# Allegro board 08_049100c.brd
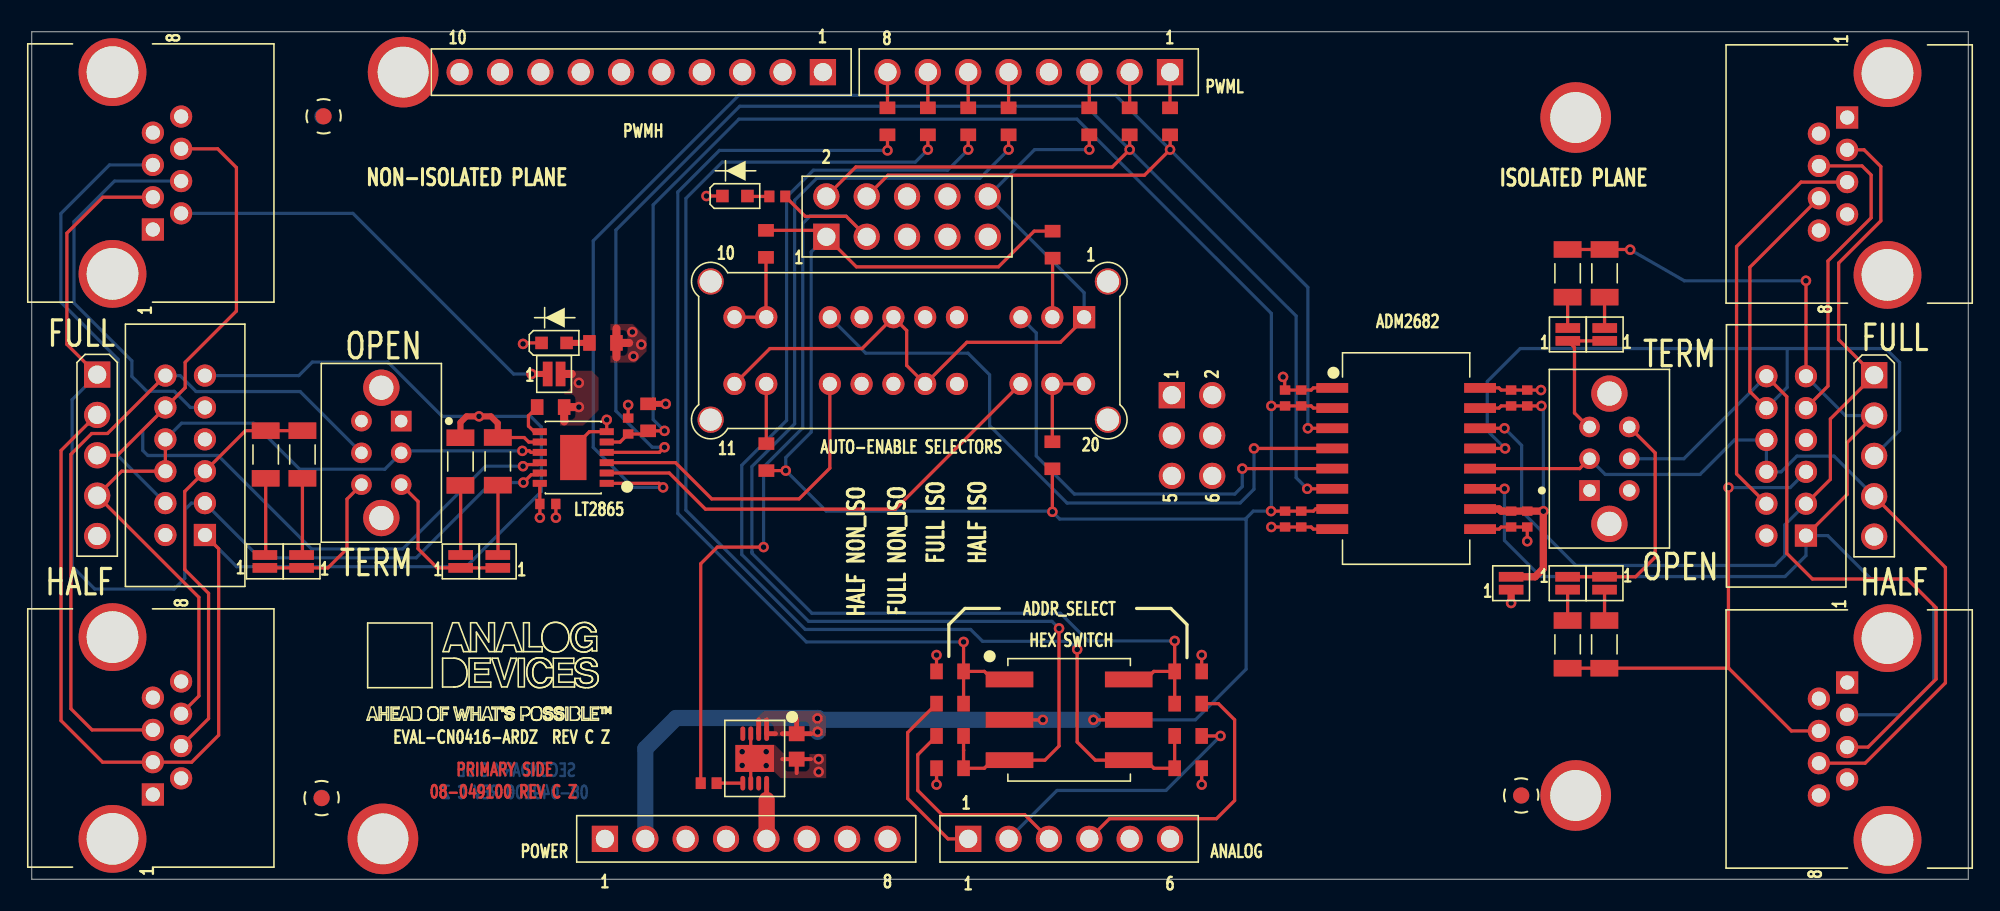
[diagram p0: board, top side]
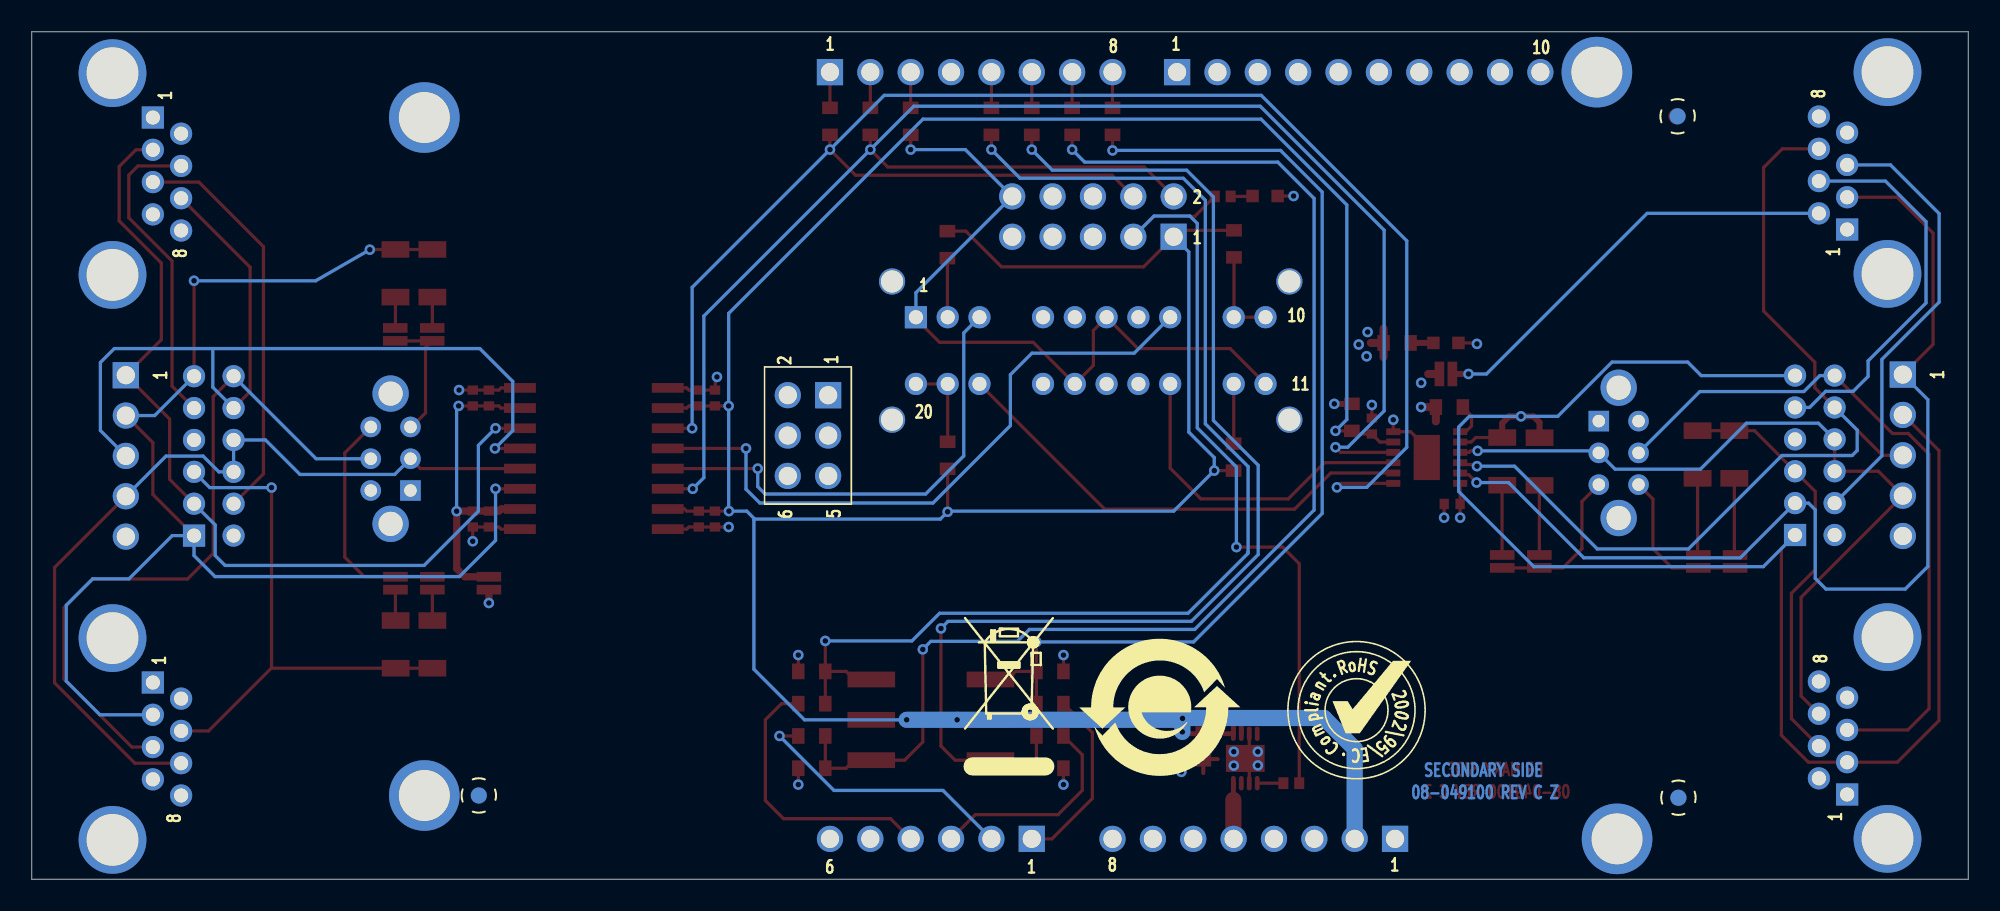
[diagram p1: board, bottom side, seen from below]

Outline 121.86 x 53.34 mm; copper layers: TOP, L2_GND, L3_PWR, BOTTOM. Coordinates in mm from the lower left corner of the outline.
Outline path: 0,53.34 0,0 121.86,0 121.86,53.34 0,53.34

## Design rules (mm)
constraint set DEFAULT: min track width 0.203

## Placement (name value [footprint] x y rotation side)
C1  1uF  [C0603]  48.13 8.36 270 top
C2  10UF  [C0402]  94.11 30.29 90 top
C4  0.1uF  [C0402]  93.09 30.29 90 top
C5  0.1uF  [C0402]  32.47 23.62 180 top
C6  10UF  [C0402]  78.87 22.67 270 top
C7  0.1uF  [C0402]  78.87 30.29 90 top
C9  0.1uF  [C0402]  79.88 30.29 90 top
C10  0.01UF  [C0402]  79.88 22.67 270 top
C11  0.1uF  [C0402]  37.53 28.52 90 top
C12  0.01UF  [C0402]  93.09 22.67 270 top
C13  0.1uF  [C0402]  94.11 22.67 270 top
DS1  SML-LX0603GW-TR  [LED0603-2]  32.87 33.76 0 top
DS2  SML-LX0603YW-TR  [LED0603-2]  44.25 43 0 top
JP1  -  [JPSLD02]  32.87 31.8 0 top
JP2  -  [JPSLD02]  93.09 18.63 90 top
JP3  -  [JPSLD02]  14.67 20 90 top
JP4  -  [JPSLD02]  16.98 20 90 top
JP5  -  [JPSLD02]  26.99 20 90 top
JP6  -  [JPSLD02]  29.32 20 90 top
JP7  -  [JPSLD02]  96.65 18.63 270 top
JP8  -  [JPSLD02]  98.97 18.63 270 top
JP9  -  [JPSLD02]  98.98 34.29 90 top
JP10  -  [JPSLD02]  96.66 34.29 90 top
NOREF  -  []  5.08 2.54 0 top
NOREF#2  -  []  -54.1 -114.3 0 top
NOREF#3  -  []  121.86 0 90 top
NOREF#4  -  []  0 53.34 270 top
NOREF#5  -  []  82.68 26.9 0 top
NOREF#6  -  []  0 0 0 top
NOREF#7  -  [unnamed#2]  22.1 2.54 0 top
NOREF#8  -  [unnamed#2]  18.24 5.11 0 top
NOREF#9  -  [unnamed#2]  18.36 48.02 0 top
NOREF#10  -  []  -54.1 -114.3 0 top
NOREF#11  -  []  0 53.34 0 top
NOREF#12  -  []  -54.1 -114.3 0 top
NOREF#13  -  []  77.34 260.67 0 top
NOREF#14  -  []  0 53.34 0 top
NOREF#15  -  [unnamed#2]  93.73 5.27 0 top
NOREF#16  -  []  -20.45 246.38 0 top
NOREF#17  -  []  5.08 2.54 0 top
NOREF#18  -  []  121.86 0 90 top
NOREF#19  -  []  0 0 0 top
NOREF#20  -  [unnamed#2]  97.16 5.27 0 top
NOREF#21  -  []  0 0 0 top
NOREF#22  -  []  121.86 53.34 180 top
NOREF#23  -  [unnamed#2]  97.16 47.94 0 top
NOREF#24  -  []  60.2 63.5 0 top
NOREF#25  -  []  121.86 0 0 top
NOREF#26  -  []  144.02 64.43 0 top
NOREF#27  -  [unnamed#2]  23.37 50.8 0 top
NOREF#28  -  []  50.88 10.82 180 bottom
NOREF#29  -  [unnamed#2]  93.73 5.27 180 bottom
NOREF#30  -  [unnamed#2]  18.24 5.13 180 bottom
NOREF#31  -  []  38.49 10.64 180 bottom
NOREF#32  -  [unnamed#2]  18.29 48.02 180 bottom
P1  TSW-105-08-G-S  [CNBERG1X5H205LD36]  115.94 31.72 270 top
P2  TSW-105-08-G-S  [CNBERG1X5H205LD36]  4.11 31.76 270 top
P3  ESQ-106-24-T-S  [CNTHFHDR1X6L620W95H545]  58.93 2.54 0 top
P4  RJHSE-5080  [CNACP-RJHSE-5080]  114.24 12.38 270 top
P5  RJHSE-5080  [CNACP-RJHSE-5080]  114.24 47.94 270 top
P6  RJHSE-5080  [CNACP-RJHSE-5080]  7.62 40.89 90 top
P7  SSQ-103-03-T-D  [CNSAMTECSSQ-103-XX-X-D]  71.74 30.47 270 bottom
P8  ESQ-108-24-T-S  [CNTHFHDR1X8L820W95H545]  36.07 2.54 0 top
P9  ESQ-110-24-T-S  [CNTHFHDR1X10L1020W95H545]  49.78 50.8 180 top
P10  ESQ-108-24-T-S  [CNTHFHDR1X8L820W95H545]  71.63 50.8 180 top
P11  TSW-105-07-G-D  [CNSAMTEC2X5H338LD36]  50 40.44 0 top
P24  RJHSE-5080  [CNACP-RJHSE-5080]  7.62 5.33 90 top
R1  165  [R0603]  35.94 33.76 180 top
R2  10K  [R0603]  32.65 29.72 180 top
R3  10K  [R0603]  64.24 39.94 270 top
R4  10K  [R0603]  46.2 39.99 270 top
R5  10K  [R0603]  46.23 26.57 90 top
R6  10K  [R0603]  64.22 26.68 90 top
R7  0  [R0603]  38.79 29.07 270 top
R8  120  [R1206]  26.97 26.29 90 top
R9  100  [R1206]  29.32 26.3 90 top
R10  120  [R1206]  14.72 26.73 90 top
R11  100  [R1206]  17.03 26.73 90 top
R12  120  [R1206]  98.97 38.14 90 top
R13  100  [R1206]  96.65 38.14 90 top
R14  120  [R1206]  96.65 14.78 270 top
R15  100  [R1206]  98.96 14.78 270 top
R16  0  [R0603]  58.93 47.7 90 top
R17  0  [R0603]  53.85 47.7 90 top
R18  0  [R0603]  61.47 47.7 90 top
R19  0  [R0603]  56.39 47.7 90 top
R20  165  [R0402]  42.6 6.05 180 top
R21  165  [R0402]  46.91 42.98 180 top
R24  0  [R0603]  71.63 47.7 90 top
R25  0  [R0603]  69.09 47.7 90 top
R26  0  [R0603]  66.55 47.7 90 top
R27  10K  [R0603]  72.77 11.05 180 top
R28  10K  [R0603]  57.78 9.02 0 top
R29  10K  [R0603]  72.77 9.02 180 top
R30  10K  [R0603]  57.78 11.05 0 top
R31  10K  [R0603]  57.78 13.08 180 top
R32  10K  [R0603]  72.77 6.99 0 top
R33  10K  [R0603]  57.78 6.99 180 top
R34  10K  [R0603]  72.77 13.08 0 top
S1  220AMB16R  [SWSMSQ283H268]  65.28 10.03 270 top
S2  SS-44D04-G 4  [SWTHL1024W366H728]  66.22 35.37 180 top
S4  MMS42  [SWTHL630W276H296]  10.9 21.67 90 top
S5  MMS42  [SWTHL630W276H296]  111.65 21.63 90 top
S6  OS202011MS2QN1  [SWTHL339W268H342]  23.25 28.84 270 top
S7  OS202011MS2QN1  [SWTHL339W268H342]  98.03 24.47 90 top
U1  ADM2682EBRIZ  [SO16WB_A]  86.49 26.48 270 top
U2  ADP7102ACPZ-3.3  [QFN8_3X3_PAD2_44X1_7]  45.49 7.6 180 top
U3  LTC2865HMSE#PBF  [MSOP12_PAD2_845X1_651]  34.07 26.54 90 top

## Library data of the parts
C1 = CAP: User Part Number: UPN; Tolerance: 10; alternate symbols: (); part number: CAP_SM-1UF,16V,10,E020596,C0603; tolerance: 10
C2 C6 = CAP: User Part Number: UPN; Tolerance: 20; alternate symbols: (C0402L_ALT); part number: CAP_SM-10UF,6.3V,20,E025264,C0402; tolerance: 20
C4 C5 C7 C9 C11 C13 = CAP: User Part Number: UPN; Tolerance: 10; alternate symbols: (); part number: CAP_SM-0.1UF,35V,10,E019488,C0402; tolerance: 10
C10 C12 = CAP: User Part Number: UPN; Tolerance: 10; alternate symbols: (); part number: CAP_SM-0.01UF,25V,10,E013688,C0402; tolerance: 10
DS1 = DIOLED: Tolerance: N/A; User Part Number: UPN; alternate symbols: (); part number: DIOLED_SM-SML-LX0603GW-TR,N/A,N/A,E018702,LED0603-2; tolerance: N/A
DS2 = DIOLED: Tolerance: N/A; User Part Number: UPN; alternate symbols: (); part number: DIOLED_SM-SML-LX0603YW-TR,2.2V,N/A,E027295,LED0603-2; tolerance: N/A
JP1-JP10 = NC2P: User Part Number: UPN; Tolerance: N/A; alternate symbols: (); part number: NC2P_SM-JPSLD02,E006230,JPSLD02; tolerance: N/A
P1 P2 = CN5P: User Part Number: UPN; Tolerance: N/A; alternate symbols: (); part number: CN5P_TH-TSW-105-08-G-S,E000855,CNBERG1X5H205LD36; tolerance: N/A
P3 = CN6P: User Part Number: UPN; Tolerance: N/A; alternate symbols: (); part number: CN6P_SM-ESQ-106-24-T-S,E033718,CNTHFHDR1X6L620W95H545; tolerance: N/A
P4-P6 P24 = CN8P_A: Tolerance: N/A; User Part Number: UPN; alternate symbols: (); part number: CN8P_A_TH-RJHSE-5080,E015308,CNACP-RJHSE-5080; tolerance: N/A
P7 = CN6P: User Part Number: UPN; Tolerance: N/A; alternate symbols: (); part number: CN6P_TH-SSQ-103-03-T-D,E027152,CNSAMTECSSQ-103-XX-X-D; tolerance: N/A
P8 P10 = CN8P_A: User Part Number: UPN; Tolerance: N/A; alternate symbols: (); part number: CN8P_A_TH-ESQ-108-24-T-S,E033714,CNTHFHDR1X8L820W95H545; tolerance: N/A
P9 = CN10P: User Part Number: UPN; Tolerance: N/A; alternate symbols: (); part number: CN10P_TH-ESQ-110-24-T-S,E033712,CNTHFHDR1X10L1020W95H545; tolerance: N/A
P11 = CN10P: User Part Number: UPN; Tolerance: N/A; alternate symbols: (); part number: CN10P_TH-TSW-105-07-G-D,E026229,CNSAMTEC2X5H338LD36; tolerance: N/A
R1 = RES: User Part Number: UPN; Tolerance: 1; alternate symbols: (R0603L); part number: RES_SM-165,E003725,1/10W,1,R0603; tolerance: 1
R2-R6 R27-R34 = RES: User Part Number: UPN; Tolerance: 1; alternate symbols: (R0603L); part number: RES_SM-10K,E003671,1/10W,1,R0603; tolerance: 1
R7 R16-R19 R24-R26 = RES: User Part Number: UPN; Tolerance: 5; alternate symbols: (R0603L); part number: RES_SM-0,E006826,1/10W,5,R0603; tolerance: 5
R8 R10 R12 R14 = RES: User Part Number: UPN; Tolerance: 1; alternate symbols: (); part number: RES_SM-120,E013413,1/4W,1,R1206; tolerance: 1
R9 R11 R13 R15 = RES: User Part Number: UPN; Tolerance: 1; alternate symbols: (); part number: RES_SM-100,E003220,1/4W,1,R1206; tolerance: 1
R20 R21 = RES: User Part Number: UPN; Tolerance: 1; alternate symbols: (R0402L); part number: RES_SM-165,E007468,1/16W,1,R0402; tolerance: 1
S1 = SWHEXCODE_6P: User Part Number: UPN; Tolerance: N/A; alternate symbols: (); part number: SWHEXCODE_6P_SM-220AMB16R,E032020,SWSMSQ283H268; tolerance: N/A
S2 = SW4P4T_V2: User Part Number: UPN; Tolerance: N/A; alternate symbols: (); part number: SW4P4T_V2_TH-SS-44D04-G 4,E033593,SWTHL1024W366H728; tolerance: N/A
S4 S5 = SW4PDT: Tolerance: N/A; User Part Number: UPN; alternate symbols: (); part number: SW4PDT_TH-MMS42,E019114,SWTHL630W276H296; tolerance: N/A
S6 S7 = SWDPDT_V2: Tolerance: N/A; User Part Number: UPN; alternate symbols: (); part number: SWDPDT_V2_TH-OS202011MS2QN1,E011304,SWTHL339W268H342; tolerance: N/A
U1 = ADM268XE: User Part Number: UPN; Tolerance: N/A; alternate symbols: (); part number: ADM268XE_SM-ADM2682EBRIZ,E019822,SO16WB_A; tolerance: N/A
U2 = ADP7102: Tolerance: N/A; User Part Number: UPN; alternate symbols: (); part number: ADP7102_SM-ADP7102ACPZ-3.3,E021573,QFN8_3X3_PAD2_44X1_7; tolerance: N/A
U3 = LINLTC2865: Tolerance: N/A; User Part Number: UPN; alternate symbols: (); part number: LINLTC2865_SM-LTC2865HMSE#PBF,E031616,MSOP12_PAD2_845X1_651; tolerance: N/A

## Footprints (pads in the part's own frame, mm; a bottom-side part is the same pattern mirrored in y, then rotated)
C0402
  rect 0.584x0.66 smd: 1(-0.5,0) 2(0.5,0)
C0603
  rect 0.94x0.991 smd: 1(-0.8,0) 2(0.8,0)
CNACP-RJHSE-5080
  round 4.267 hole 3.251 unplated: (-2.794,2.54) (9.906,2.54)
  rect 1.397x1.397 hole 0.889: 1(0,0)
  round 1.397 hole 0.889: 2(1.016,-1.778) 3(2.032,0) 4(3.048,-1.778) 5(4.064,0) 6(5.08,-1.778) 7(6.096,0) 8(7.112,-1.778)
CNBERG1X5H205LD36
  rect 1.651x1.651 hole 1.143: 1(0,0)
  round 1.651 hole 1.143: 2(2.54,0) 3(5.08,0) 4(7.62,0) 5(10.16,0)
CNSAMTEC2X5H338LD36
  rect 1.651x1.651 hole 1.143: 1(0,0)
  round 1.651 hole 1.143: 2(0,2.54) 3(2.54,0) 4(2.54,2.54) 5(5.08,0) 6(5.08,2.54) 7(7.62,0) 8(7.62,2.54) 9(10.16,0) 10(10.16,2.54)
CNSAMTECSSQ-103-XX-X-D
  rect 1.651x1.651 hole 1.143: 1(0,0)
  round 1.651 hole 1.143: 2(0,-2.54) 3(2.54,0) 4(2.54,-2.54) 5(5.08,0) 6(5.08,-2.54)
CNTHFHDR1X6L620W95H545
  rect 1.651x1.651 hole 1.143: 1(0,0)
  round 1.651 hole 1.143: 2(2.54,0) 3(5.08,0) 4(7.62,0) 5(10.16,0) 6(12.7,0)
CNTHFHDR1X8L820W95H545
  rect 1.651x1.651 hole 1.143: 1(0,0)
  round 1.651 hole 1.143: 2(2.54,0) 3(5.08,0) 4(7.62,0) 5(10.16,0) 6(12.7,0) 7(15.24,0) 8(17.78,0)
CNTHFHDR1X10L1020W95H545
  rect 1.651x1.651 hole 1.143: 1(0,0)
  round 1.651 hole 1.143: 2(2.54,0) 3(5.08,0) 4(7.62,0) 5(10.16,0) 6(12.7,0) 7(15.24,0) 8(17.78,0) 9(20.32,0) 10(22.86,0)
JPSLD02
  rect 0.61x1.549 smd: 1(-0.406,0) 2(0.406,0)
LED0603-2
  rect 0.787x0.787 smd: A(0.787,0) C(-0.787,0)
MSOP12_PAD2_845X1_651
  rect 0.432x0.889 smd: 1(-1.625,-2.107) 2(-0.975,-2.107) 3(-0.325,-2.107) 4(0.325,-2.107) 5(0.975,-2.107) 6(1.625,-2.107) 7(1.625,2.107) 8(0.975,2.107) 9(0.325,2.107) 10(-0.325,2.107) 11(-0.975,2.107) 12(-1.625,2.107)
  rect 2.845x1.651 smd: PAD(0,0)
QFN8_3X3_PAD2_44X1_7
  oval 0.305x0.914 smd: 1(-0.75,-1.557) 2(-0.25,-1.557) 3(0.25,-1.557) 4(0.75,-1.557) 5(0.75,1.557) 6(0.25,1.557) 7(-0.25,1.557) 8(-0.75,1.557)
  rect 2.438x1.702 smd: PAD(0,0)
R0402
  rect 0.635x0.737 smd: 1(-0.5,0) 2(0.5,0)
R0603
  rect 0.787x0.991 smd: 1(-0.85,0) 2(0.85,0)
R1206
  rect 1.041x1.753 smd: 1(-1.5,0) 2(1.5,0)
SO16WB_A
  rect 0.61x2.007 smd: 1(-4.445,-4.65) 2(-3.175,-4.65) 3(-1.905,-4.65) 4(-0.635,-4.65) 5(0.635,-4.65) 6(1.905,-4.65) 7(3.175,-4.65) 8(4.445,-4.65) 9(4.445,4.65) 10(3.175,4.65) 11(1.905,4.65) 12(0.635,4.65) 13(-0.635,4.65) 14(-1.905,4.65) 15(-3.175,4.65) 16(-4.445,4.65)
SWSMSQ283H268
  rect 0.991x2.997 smd: 1(-2.54,-3.751) 2(2.54,3.751) 4(2.54,-3.751) 8(-2.54,3.751) C1(0,-3.751) C2(0,3.751)
SWTHL339W268H342
  round 2.286 hole 1.524 unplated: (-2.1,-1.25) (6.1,-1.25)
  rect 1.295x1.295 hole 0.787: 1(0,0)
  round 1.295 hole 0.787: 2(2,0) 3(4,0) 4(0,-2.5) 5(2,-2.5) 6(4,-2.5)
SWTHL630W276H296
  rect 1.397x1.397 hole 0.889: 1(0,0)
  round 1.397 hole 0.889: 2(2.007,0) 3(4.013,0) 4(6.02,0) 5(8.026,0) 6(10.033,0) 7(0,2.489) 8(2.007,2.489) 9(4.013,2.489) 10(6.02,2.489) 11(8.026,2.489) 12(10.033,2.489)
SWTHL1024W366H728
  round 1.651 hole 1.397 unplated: (-1.5,6.45) (-1.5,-2.25) (23.5,6.45) (23.5,-2.25)
  rect 1.397x1.397 hole 0.889: 1(0,0)
  round 1.397 hole 0.889: 2(2,0) 3(4,0) 4(8,0) 5(10,0) 6(12,0) 7(14,0) 8(16,0) 9(20,0) 10(22,0) 11(22,4.2) 12(20,4.2) 13(16,4.2) 14(14,4.2) 15(12,4.2) 16(10,4.2) 17(8,4.2) 18(4,4.2) 19(2,4.2) 20(0,4.2)
unnamed#2
  round 4.445 hole 3.2 unplated: (0,0)

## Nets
3V3D: JP1.2(N2) P8.4 R1.1 R2.1
5V_ARD: C5.2(N2) P8.5 P11.9(N9) R7.1 U2.8 U3.12
DGND: C1.2(N2) C5.1 C6.2(N2) C7.2(N2) C9.2(N2) C10.2(N2) C11.2(N2) DS1.C DS2.C P2.5(N5) P6.7 P6.8(N8) P7.6(N6) P8.6 P8.7 P9.7 P11.5 P11.7 P24.7 P24.8(N8) R31.2(N2) R32.2(N2) R33.2(N2) R34.2(N2) S2.4 S2.5 S2.7 S2.14 S2.15 S2.17 U1.1 U1.8 U2.3 U2.6 U2.PAD U3.6 U3.PAD
GND_ISO: C2.2(N2) C4.2(N2) C12.2(N2) C13.2(N2) P1.5(N5) P4.7 P4.8(N8) P5.7 P5.8(N8) U1.9 U1.16
ADDR0: R17.1 R30.2(N2) R31.1 S1.1
ADDR1: R19.1 R29.2(N2) R32.1 S1.2
ADDR2: R16.1 R28.2(N2) R33.1 S1.4
ADDR3: R18.1 R27.2(N2) R34.1 S1.8
AI: P1.1 P5.3 S5.2 U1.14
AI_F: P4.4 R14.2(N2) R15.2(N2) S5.3
ANI: P2.1 P6.3 S4.2 U3.11
ANI_F: P24.4 R10.2(N2) R11.2(N2) S4.3
BI: P1.3 P5.6 S5.11 U1.13
BI_F: P4.5 S5.12(NO4) S7.5
BNI: P2.3 P6.6 S4.11 U3.10
BNI_F: P24.5 S4.12(NO4) S6.5
DE_EN: P11.10 R26.1 S2.1 S2.6 S2.11 S2.16(NO4_3)
DEI: S2.3 U1.5
DENI: S2.13 U3.3
I_PWR: JP2.1 P4.1 P4.2 P5.1 P5.2
IOREF: C1.1 C6.1 C7.1 C9.1 C10.1 C11.1 P8.2 P11.1 R3.1 R4.1 R5.1 R6.1 R7.2(N2) S1.C1 S1.C2 U1.2 U1.7 U2.1(VOUT) U2.2 U3.5
LDO_EN: P11.3 R20.2(N2) R21.1
NI_PWR: JP1.1 P6.1 P6.2 P24.1 P24.2
REI: S2.8 U1.4
RENI: S2.18 U3.2
RX: P11.4 R24.1 U1.3 U3.1
TX: P11.2 R25.1 U1.6 U3.4
UNNAMED_2_LINLTC2865_I2_SLON: R2.2(N2) U3.7
UNNAMED_2_NC2P_I177_N1: JP5.1 JP6.1 S6.3
UNNAMED_2_NC2P_I178_N1: JP3.1 JP4.1 S6.6
UNNAMED_2_NC2P_I179_N1: JP7.1 JP8.1 S7.6
UNNAMED_2_NC2P_I180_N1: JP9.1 JP10.1 S7.3
UNNAMED_2_NC2P_I183_N2: JP7.2(N2) R14.1
UNNAMED_2_RES_I129_N1: JP3.2(N2) R10.1
UNNAMED_2_RES_I130_N1: JP5.2(N2) R8.1
UNNAMED_2_RES_I131_N1: JP4.2(N2) R11.1
UNNAMED_2_RES_I132_N1: JP6.2(N2) R9.1
UNNAMED_2_RES_I133_N1: JP8.2(N2) R15.1
UNNAMED_2_RES_I135_N1: JP9.2(N2) R12.1
UNNAMED_2_RES_I136_N1: JP10.2(N2) R13.1
UNNAMED_2_RES_I168_N2: R3.2(N2) S2.2
UNNAMED_2_RES_I169_N2: R4.2(N2) S2.9 S2.10
UNNAMED_2_RES_I170_N2: R5.2(N2) S2.12
UNNAMED_2_RES_I171_N2: R6.2(N2) S2.19 S2.20
UNNAMED_7_ADP7102_I80_ENUVLO: R20.1 U2.5
UNNAMED_7_CN6P_I94_N1: P3.1 R30.1
UNNAMED_7_CN6P_I94_N2: P3.2 R29.1
UNNAMED_7_CN6P_I94_N3: P3.3 R28.1
UNNAMED_7_CN6P_I94_N4: P3.4 R27.1
UNNAMED_7_CN8PA_I95_N1: P10.1 R24.2(N2)
UNNAMED_7_CN8PA_I95_N2: P10.2 R25.2(N2)
UNNAMED_7_CN8PA_I95_N3: P10.3 R26.2(N2)
UNNAMED_7_CN8PA_I95_N5: P10.5 R18.2(N2)
UNNAMED_7_CN8PA_I95_N6: P10.6 R16.2(N2)
UNNAMED_7_CN8PA_I95_N7: P10.7 R19.2(N2)
UNNAMED_7_CN8PA_I95_N8: P10.8(N8) R17.2(N2)
UNNAMED_7_DIOLED_I78_P: DS1.A(P) R1.2(N2)
UNNAMED_7_DIOLED_I90_P: DS2.A(P) R21.2(N2)
VISO: C2.1 C4.1 C12.1 C13.1 JP2.2(N2) U1.10 U1.15
YI: P1.2 P4.3 R12.2(N2) R13.2(N2) S5.1 S5.6 U1.11
YI_F: P5.4 S5.5
YNI: P2.2 P24.3 R8.2(N2) R9.2(N2) S4.1 S4.6 U3.8
YNI_F: P6.4 S4.5
ZI: P1.4 P4.6 S5.9 S5.10 S7.2 U1.12(Z)
ZI_F: P5.5 S5.8
ZNI: P2.4 P24.6 S4.9 S4.10 S6.2 U3.9(Z)
ZNI_F: P6.5 S4.8

Pads without a net: P3 5 6; P7 1 2 3 4 5; P8 1 3 8; P9 1 2 3 4 5 6 8 9 10; P10 4; P11 6 8; S4 4 7; S5 4 7; S6 1 4; S7 1 4; U2 4 7

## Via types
v1: diameter 0.66, hole 0.356, TOP to BOTTOM, 68 vias

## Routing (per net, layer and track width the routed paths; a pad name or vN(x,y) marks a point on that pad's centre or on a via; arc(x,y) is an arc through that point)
3V3D: length 8.4
  TOP w0.508: 34.3,29.72 R2.1 33.5,28.82 ; JP1.2 33.99,31.8 ; R1.1 37.59,33.76 ; R1.1 36.79,34.66 ; R1.1 36.79,32.85
  L3_PWR w0.254: 43.69,1.41 P8.4 ; P8.4 43.69,3.67 ; P8.4 42.56,2.54
  vias: v1(34.43,31.24) v1(34.43,29.72) v1(37.8,34.44) v1(37.86,32.91) v1(38.35,33.66)
5V_ARD: length 14.7
  TOP w0.203: U3.12 31.97,23.63 C5.2 v1(31.97,22.76)
  TOP w0.305: 46.24,4.99 U2.8
  TOP w0.381: R7.1 v1(39.89,29.92)
  TOP w1.016: 46.24,4.99 46.24,2.55 P8.5
  L3_PWR w0.254: 60.16,39.31 P11.9 ; P11.9 60.16,41.57 ; P11.9 59.03,40.44 ; P11.9 61.29,40.44 ; 46.23,1.41 P8.5 ; P8.5 46.23,3.67 ; P8.5 47.36,2.54
DGND: length 83.4
  TOP w0.203: R34.2 v1(73.62,14.11) ; C11.2 v1(37.53,29.85) ; U1.1 80.64,30.92 80.51,30.79 C9.2 C7.2 78.85,30.81 78.85,31.51 v1(78.74,31.62) ; DS2.C v1(42.46,43) ; R31.2 56.94,13.18 56.93,13.18 v1(56.93,14.11) ; C5.1 32.98,23.61 v1(32.98,22.76) ; v1(30.91,33.69) 30.98,33.76 DS1.C ; R33.2 v1(56.94,5.96) ; v1(78,22.17) C6.2 C10.2 80.51,22.17 80.64,22.03 U1.8 ; v1(36.18,28.92) U3.6 35.09,28.17 34.07,27.15 U3.PAD ; v1(73.62,5.96) 73.62,6.22 73.62,6.22 R32.2 ; U2.3 45.24,7.85 U2.PAD 45.24,7.35 U2.6
  TOP w0.254: 48.13,6.68 C1.2 ; C1.2 49.04,7.56 ; C1.2 47.23,7.56
  L2_GND w0.254: 54.22,32.18 S2.15 54.22,30.17 ; 48.77,1.41 P8.6 ; P8.6 49.9,2.54 ; P8.6 47.64,2.54 ; P8.6 48.77,3.67 ; P7.6 75.41,25.39 ; P7.6 73.15,25.39 ; P7.6 74.28,24.26 ; P7.6 74.28,26.52 ; P8.7 51.31,3.67 ; P8.7 51.31,1.41 ; P8.7 52.44,2.54 ; P8.7 50.18,2.54 ; P24.7 8.62,11.43 ; P24.7 6.62,11.43 ; P24.7 7.62,12.43 ; 4.11,20.47 P2.5 ; P2.5 4.11,22.73 ; P2.5 2.98,21.6 ; P2.5 5.25,21.6 ; S2.4 58.22,36.38 ; S2.4 58.22,34.37 ; S2.4 59.22,35.37 ; 52.22,34.37 S2.7 52.22,36.38 ; 8.39,48.01 P6.8 ; P6.8 10.4,48.01 ; P6.8 9.4,49.01 ; 56.22,36.38 S2.5 56.22,34.37 ; S2.17 59.22,31.17 ; S2.17 58.22,30.17 ; S2.17 58.22,32.18 ; P11.7 57.62,41.57 ; P11.7 57.62,39.31 ; P11.7 58.75,40.44 ; P11.7 56.49,40.44 ; 6.62,46.99 P6.7 ; P6.7 7.62,47.99 ; P6.7 8.62,46.99 ; 34.54,49.67 P9.7 ; P9.7 34.54,51.93 ; P9.7 33.41,50.8 ; P9.7 35.67,50.8 ; P24.8 9.4,13.45 ; P24.8 10.4,12.45 ; P24.8 8.39,12.45 ; 52.22,32.18 S2.14 52.22,30.17 ; 53.95,40.44 P11.5 ; P11.5 56.21,40.44 ; P11.5 55.08,41.57 ; P11.5 55.08,39.31
  vias: v1(44.7,8.03) v1(44.7,7.16) v1(46.22,8.03) v1(46.22,7.15) v1(49.52,7.56) v1(49.52,6.76)
GND_ISO: length 24.4
  TOP w0.203: v1(94.97,30.79) C2.2 C4.2 92.46,30.79 92.33,30.92 U1.16 ; v1(94.11,21.27) C13.2 C12.2 92.46,22.17 92.33,22.03 U1.9
  L2_GND w0.254: 114.24,5.28 P4.7 ; P4.7 113.23,6.29 ; P4.7 115.24,6.29 ; 114.24,40.84 P5.7 ; P5.7 115.24,41.85 ; P5.7 113.23,41.85 ; 115.94,20.43 P1.5 ; P1.5 115.94,22.7 ; P1.5 114.81,21.56 ; P1.5 117.07,21.56 ; 112.46,39.83 P5.8 ; P5.8 111.45,40.83 ; P5.8 113.46,40.83 ; 111.45,5.27 P4.8 ; P4.8 112.46,4.27 ; P4.8 113.46,5.27
ADDR0: length 63.8
  TOP w0.203: v1(58.64,14.94) 58.64,13.08 R31.1 ; R31.1 59.94,13.08 60.45,12.57 61.53,12.57 ; R31.1 58.64,13.08 58.64,11.05 R30.2 ; R17.1 v1(53.85,45.87)
  BOTTOM w0.203: v1(53.85,45.87) 43.27,45.87 40.65,43.26 40.65,23.03 48.74,14.94 v1(58.64,14.94)
ADDR1: length 80
  TOP w0.203: R29.2 71.92,9.02 71.92,6.99 R32.1 70.61,6.99 70.1,7.49 S1.2 66.93,7.49 65.79,8.64 v1(65.79,14.47) ; R19.1 v1(56.39,45.92)
  BOTTOM w0.203: v1(65.79,14.47) 65.28,14.97 59.83,14.97 59.08,15.72 48.67,15.72 41.16,23.24 41.16,42.85 43.45,45.14 55.6,45.14 v1(56.39,45.92)
ADDR2: length 75.2
  TOP w0.203: v1(64.64,15.79) 64.64,8.38 63.75,7.49 S1.4 60.45,7.49 59.94,6.99 R33.1 58.63,8.13 58.64,8.13 58.63,8.13 R28.2 ; R16.1 v1(58.93,45.92)
  BOTTOM w0.203: v1(64.64,15.79) 64.2,16.23 48.88,16.23 44.68,20.44 44.68,26.06 47.5,28.87 47.5,42.95 49.18,44.63 57.63,44.63 v1(58.93,45.92)
ADDR3: length 75
  TOP w0.203: R34.1 v1(71.92,15) ; R34.1 70.61,13.08 70.1,12.57 69.03,12.57 ; R34.1 R27.2 ; R18.1 v1(61.47,45.92)
  BOTTOM w0.203: v1(61.47,45.92) 59.66,44.12 49.39,44.12 48.01,42.74 48.01,28.66 45.31,25.97 45.31,20.6 45.32,20.59 45.32,20.51 49.09,16.74 64.73,16.74 66.47,15 v1(71.92,15)
AI: length 56.8
  TOP w0.203: S5.2 113.18,25.17 113.18,28.97 P1.1 113.7,33.96 113.7,38.79 116.36,41.44 116.36,44.86 115.3,45.91 P5.3 ; U1.14 v1(92.67,28.38)
  BOTTOM w0.203: v1(92.67,28.38) 93.75,27.31 93.75,23.16 97.17,19.75 109.69,19.75 110.31,20.37 110.31,22.3 S5.2
AI_F: length 34.1
  TOP w0.203: v1(106.77,24.65) 106.77,13.3 106.78,13.28 ; P4.4 110.73,9.33 106.78,13.28 ; 106.78,13.28 R15.2 R14.2
  BOTTOM w0.203: v1(106.77,24.65) 110.66,24.65 S5.3
ANI: length 67.2
  TOP w0.203: P2.1 2.21,33.67 2.21,40.67 4.47,42.93 P6.3 ; v1(30.94,24.97) 31.43,25.46 31.86,25.46 U3.11
  BOTTOM w0.203: v1(30.94,24.97) 28.93,24.97 24.19,20.23 14.34,20.23 S4.2 10.05,23.67 9.63,23.25 9.63,18.94 8.95,18.26 3.96,18.26 2.54,19.68 2.54,30.19 P2.1
ANI_F: length 26.4
  TOP w0.203: R11.2 R10.2 13.45,28.23 S4.3 9.63,24.41 9.63,19.49 11.13,17.99 11.13,10.11 P24.4
BI: length 59.7
  TOP w0.203: S5.11 108.12,30.7 108.12,38.52 P5.6 ; U1.13 v1(92.71,27.11)
  BOTTOM w0.203: S5.11 110.46,30.96 110.46,33.4 ; P1.3 117.54,28.24 117.54,32.52 116.66,33.4 110.46,33.4 ; 110.46,33.4 93.66,33.4 91.59,31.33 91.59,28.23 v1(92.71,27.11)
BI_F: length 45.1
  TOP w0.203: P4.5 115.56,8.32 119.84,12.6 119.84,17.08 118.02,18.9 112.05,18.9 110.44,20.51 110.44,30.38 S5.12
  BOTTOM w0.203: S7.5 103.96,26.47 S5.12
BNI: length 59.6
  TOP w0.203: P6.6 11.7,45.97 12.88,44.79 12.88,35.76 9.65,32.54 9.65,30.94 S4.11 5.4,26.68 P2.3 ; U3.10 31.85,26.1 31.01,26.1 v1(30.91,26)
  BOTTOM w0.203: v1(30.91,26) 28.55,26 23.34,20.79 17.6,20.79 11.72,26.67 7.3,26.67 6.99,26.99 6.99,28.27 S4.11
BNI_F: length 44.1
  TOP w0.203: S4.12 4.76,28.05 3.77,28.05 2.46,26.75 2.46,10.73 3.8,9.4 P24.5
  BOTTOM w0.203: S4.12 9.33,31.7 10.34,30.7 16.89,30.7 S6.5
DE_EN: length 47.2
  TOP w0.203: S2.11 46.45,33.4 52.25,33.4 S2.6 55.05,34.54 55.05,32.34 S2.16 58.84,33.79 64.73,33.79 66.22,35.28 S2.1 ; R26.1 v1(66.55,45.92)
  BOTTOM w0.203: S2.1 66.22,36.92 P11.10 63.11,45.92 v1(66.55,45.92)
DEI: length 30.1
  TOP w0.203: U1.5 v1(76.17,25.84)
  BOTTOM w0.203: S2.3 63.21,34.38 63.21,26.64 65.61,24.24 75.7,24.24 76.17,24.71 v1(76.17,25.84)
DENI: length 21.1
  TOP w0.203: S2.13 50.22,25.87 48.29,23.94 42.79,23.94 40.51,26.22 U3.3
I_PWR: length 12.9
  TOP w0.457: v1(93.09,17.39) JP2.1
  L3_PWR w0.254: P4.2 112.46,12.37 ; P4.2 111.45,11.37 ; P4.2 113.46,11.37 ; 113.23,12.38 P4.1 ; P4.1 114.24,13.39 ; P4.1 115.24,12.38 ; P5.1 114.24,48.95 ; P5.1 113.23,47.94 ; P5.1 115.24,47.94 ; P5.2 113.46,46.93 ; P5.2 112.46,47.93 ; P5.2 111.45,46.93
IOREF: length 221.8
  TOP w0.203: R3.1 63.08,40.79 60.83,38.54 51.89,38.54 P11.1 49.59,40.84 R4.1 ; R6.1 v1(64.22,23.13) ; S1.C1 v1(63.63,10.03) ; U3.5 37.02,27.52 C11.1 38.59,28.02 R7.2 v1(39.81,28.22) ; v1(66.8,10.03) S1.C2 ; R5.1 v1(47.45,25.72) ; v1(77.99,23.17) C6.1 C10.1 80.65,23.17 80.78,23.3 U1.7 ; v1(78,29.79) C7.1 C9.1 80.51,29.79 80.64,29.65 U1.2
  TOP w0.305: C1.1 49.04,9.16 ; C1.1 48.13,10.04 ; C1.1 47.23,9.16 ; 46.24,10.02 U2.1 46.8,9.16 ; U2.2 45.74,10.02
  BOTTOM w0.203: 76.37,22.67 76.42,22.62 76.42,13.22 73.23,10.03 v1(66.8,10.03) ; 76.37,22.67 64.68,22.67 v1(64.22,23.13) 64.18,23.17 50,23.17 v1(47.45,25.72) 47.45,26.54 49.05,28.14 49.05,39.48 P11.1 ; 76.37,22.67 76.87,23.17 v1(77.99,23.17) 78,23.19 v1(78,29.79) 78,35.61 65.77,47.84 44.5,47.84 39.1,42.44 39.1,28.93 v1(39.81,28.22)
  BOTTOM w1.016: 49.47,10.15 40.54,10.15 38.61,8.22 P8.2 ; 49.47,10.15 v1(49.44,10.12) 49.45,10.11 v1(49.45,9.27) ; 49.47,10.15 49.58,10.03 v1(63.63,10.03) v1(66.8,10.03)
LDO_EN: length 50.5
  TOP w0.203: R21.1 48.67,41.72 51.26,41.72 P11.3 ; v1(46.05,20.9) 43.14,20.9 42.1,19.86 R20.2
  BOTTOM w0.203: v1(46.05,20.9) 46.05,25.95 48.51,28.41 48.51,41.27 48.98,41.74 51.23,41.74 P11.3
NI_PWR: length 39.3
  TOP w0.381: v1(31.45,31.8) JP1.1
  L3_PWR w0.254: P6.2 10.4,41.91 ; P6.2 8.39,41.91 ; P6.2 9.4,40.91 ; 7.62,39.89 P6.1 ; P6.1 8.62,40.89 ; P6.1 6.62,40.89 ; 9.4,5.35 P24.2 ; P24.2 10.4,6.35 ; P24.2 8.39,6.35 ; 7.62,4.33 P24.1 ; P24.1 6.62,5.33 ; P24.1 8.62,5.33
  BOTTOM w0.203: P6.2 20.21,41.91 30.32,31.8 v1(31.45,31.8)
REI: length 41.3
  TOP w0.203: v1(76.91,27.11) U1.4
  BOTTOM w0.203: v1(76.91,27.11) 76.91,24.55 76.04,23.68 65.15,23.68 60.27,28.55 60.27,31.75 58.92,33.11 52.48,33.11 S2.8
RENI: length 30.2
  TOP w0.203: S2.18 54.34,23.29 42.39,23.29 40.12,25.57 U3.2
RX: length 107.5
  TOP w0.203: U1.3 v1(80.3,28.38) ; P11.4 53.87,44.31 70.01,44.31 v1(71.63,45.92) 71.64,45.93 71.64,46.84 R24.1 ; v1(39.73,24.66) 39.47,24.92 U3.1
  BOTTOM w0.203: v1(39.73,24.66) 37.85,24.66 35.33,27.18 35.33,40.18 44.49,49.34 68.21,49.34 v1(71.63,45.92) 80.3,37.25 v1(80.3,28.38)
TX: length 104.6
  TOP w0.203: U1.6 v1(80.26,24.57) ; R25.1 v1(69.09,45.92) 67.99,44.83 51.85,44.83 P11.2 ; v1(39.81,27.19) 39.49,26.87 U3.4
  BOTTOM w0.203: v1(39.81,27.19) 39.04,27.19 36.75,29.48 36.75,40.86 44.55,48.65 66.36,48.65 v1(69.09,45.92) 79.56,35.45 79.56,25.27 v1(80.26,24.57)
UNNAMED_2_LINLTC2865_I2_SLON: length 2.3
  TOP w0.203: U3.7 31.61,28.17 31.25,28.52 31.25,29.17 R2.2
UNNAMED_2_NC2P_I177_N1: length 10
  TOP w0.203: S6.3 24.31,23.77 24.31,20.8 25.51,19.6 JP5.1 JP6.1
UNNAMED_2_NC2P_I178_N1: length 10.1
  TOP w0.203: S6.6 19.84,23.93 19.84,20.8 18.63,19.6 JP4.1 JP3.1
UNNAMED_2_NC2P_I179_N1: length 14.9
  TOP w0.203: S7.6 102.16,26.83 102.16,20.27 100.93,19.04 JP8.1 JP7.1
UNNAMED_2_NC2P_I180_N1: length 8.3
  TOP w0.203: S7.3 97.96,28.47 97.08,29.35 97.08,33.46 JP10.1 JP9.1
UNNAMED_2_NC2P_I183_N2: length 1.9
  TOP w0.203: JP7.2 R14.1
UNNAMED_2_RES_I129_N1: length 4.9
  TOP w0.203: JP3.2 14.72,20.41 R10.1
UNNAMED_2_RES_I130_N1: length 4.4
  TOP w0.203: R8.1 26.99,24.78 JP5.2
UNNAMED_2_RES_I131_N1: length 4.9
  TOP w0.203: R11.1 17.03,20.41 JP4.2
UNNAMED_2_RES_I132_N1: length 4.4
  TOP w0.203: JP6.2 29.34,20.42 29.34,24.79 R9.1
UNNAMED_2_RES_I133_N1: length 1.9
  TOP w0.203: JP8.2 98.97,16.3 R15.1
UNNAMED_2_RES_I135_N1: length 1.9
  TOP w0.203: JP9.2 98.97,34.71 R12.1
UNNAMED_2_RES_I136_N1: length 1.9
  TOP w0.203: R13.1 96.65,34.71 JP10.2
UNNAMED_2_RES_I168_N2: length 3.7
  TOP w0.203: S2.2 64.24,35.39 R3.2
UNNAMED_2_RES_I169_N2: length 5.8
  TOP w0.203: S2.10 S2.9 46.2,35.39 R4.2
UNNAMED_2_RES_I170_N2: length 3.8
  TOP w0.203: S2.12 46.22,27.43 R5.2
UNNAMED_2_RES_I171_N2: length 5.6
  TOP w0.203: R6.2 64.22,27.54 S2.19 S2.20
UNNAMED_7_ADP7102_I80_ENUVLO: length 1.6
  TOP w0.203: U2.5 R20.1
UNNAMED_7_CN6P_I94_N1: length 11.6
  TOP w0.203: R30.1 55.12,9.23 55.12,5.08 57.66,2.54 P3.1
UNNAMED_7_CN6P_I94_N2: length 17.2
  TOP w0.203: R29.1 v1(74.8,9.02)
  BOTTOM w0.203: P3.2 64.52,5.59 71.37,5.59 v1(74.8,9.02)
UNNAMED_7_CN6P_I94_N3: length 13.4
  TOP w0.203: R28.1 55.75,7.83 55.75,5.59 57.28,4.06 62.48,4.06 P3.3
UNNAMED_7_CN6P_I94_N4: length 17.7
  TOP w0.203: R27.1 74.68,11.05 75.69,10.03 75.69,4.95 74.55,3.81 67.82,3.81 P3.4
UNNAMED_7_CN8PA_I95_N1: length 2.2
  TOP w0.203: R24.2 P10.1
UNNAMED_7_CN8PA_I95_N2: length 2.2
  TOP w0.203: R25.2 P10.2
UNNAMED_7_CN8PA_I95_N3: length 2.2
  TOP w0.203: R26.2 P10.3
UNNAMED_7_CN8PA_I95_N5: length 2.2
  TOP w0.203: R18.2 P10.5
UNNAMED_7_CN8PA_I95_N6: length 2.2
  TOP w0.203: R16.2 P10.6
UNNAMED_7_CN8PA_I95_N7: length 2.2
  TOP w0.203: R19.2 P10.7
UNNAMED_7_CN8PA_I95_N8: length 2.2
  TOP w0.203: R17.2 P10.8
UNNAMED_7_DIOLED_I78_P: length 1.4
  TOP w0.381: R1.2 DS1.A
UNNAMED_7_DIOLED_I90_P: length 1.4
  TOP w0.203: R21.2 45.06,42.98 DS2.A
VISO: length 20.5
  TOP w0.203: U1.15 92.33,29.65 92.46,29.79 C4.1 C2.1 v1(95,29.79)
  TOP w0.457: 95.12,23.17 94.11,23.17 C13.1 C12.1 92.46,23.17 92.33,23.3 U1.10 ; 95.12,23.17 v1(95.12,23.16) ; 95.12,23.17 95.12,19.55 94.6,19.04 JP2.2
  BOTTOM w0.203: v1(95,29.79) 95.12,29.66 v1(95.12,23.16)
YI: length 83.7
  TOP w0.203: S5.6 v1(111.65,37.67) ; R13.2 R12.2 100.57,39.64 v1(100.58,39.62) ; S5.1 114.24,24.22 114.24,27.48 P1.2 ; U1.11 v1(92.67,24.57)
  BOTTOM w0.203: v1(92.67,24.57) 92.67,21.32 94.95,19.05 110.33,19.05 111.65,20.37 S5.1 113.02,21.63 115.74,18.91 118.02,18.91 119.68,17.25 119.68,12.47 117.56,10.35 P4.3 ; S5.6 114.12,29.18 P1.2 ; v1(111.65,37.67) 111.64,37.67 103.99,37.67 v1(100.58,39.62)
YI_F: length 19.9
  TOP w0.203: P5.4 115.18,44.89 115.75,44.32 115.75,41.63 113.03,38.91 113.03,31.04 S5.5
YNI: length 103.4
  TOP w0.203: U3.8 31.27,27.52 30.99,27.8 R9.2 ; S4.1 11.76,20.8 11.76,9.07 10.06,7.37 P24.3 4.46,7.37 1.84,9.98 1.84,26.99 3.52,28.66 3.56,28.66 P2.2
  TOP w0.381: R9.2 29.32,28.7 28.89,29.13 v1(28.14,29.13) 27.36,29.13 26.97,28.75 R8.2
  BOTTOM w0.203: S4.6 16.8,31.7 17.65,32.55 22.41,32.55 25.83,29.13 v1(28.14,29.13) 31.39,29.13 32.07,28.46 32.07,24.41 27.33,19.67 12.89,19.67 S4.1
YNI_F: length 24.5
  BOTTOM w0.203: P6.4 5.21,43.94 2.65,41.39 2.65,36.27 6.3,32.63 6.3,31.65 7.24,30.71 8.97,30.71 9.98,29.69 S4.5
ZI: length 53.5
  TOP w0.203: P4.6 115.37,7.3 120.42,12.36 120.42,19.62 P1.4 ; U1.12 97.4,25.84 S7.2
  BOTTOM w0.203: P1.4 113.41,26.63 111.07,26.63 110.08,25.64 S5.9 S5.10 107.15,27.65 104.98,25.48 99.02,25.48 S7.2
ZI_F: length 25.6
  TOP w0.203: S5.8 107.28,25.51 107.28,39.81 111.34,43.88 P5.5
ZNI: length 49.5
  TOP w0.203: P24.6 10.52,11.53 10.52,17.74 P2.4 5.65,25.68 S4.9 S4.10 ; v1(30.87,26.96) 31.31,26.96 31.41,26.87 U3.9
  BOTTOM w0.203: S4.10 9.42,28.7 13.96,28.7 16.85,25.81 22.22,25.81 S6.2 23.37,26.96 v1(30.87,26.96)
ZNI_F: length 28
  BOTTOM w0.203: S4.8 5.43,26.65 5.43,32.72 1.83,36.32 1.83,41.9 4.89,44.96 P6.5

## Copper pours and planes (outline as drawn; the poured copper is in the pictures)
3V3D on TOP: 35.67,29.53 35.67,31.56 35.23,32 33.24,32 33.24,28.55 34.7,28.55
3V3D on TOP: 38.68,33.22 38.68,34.09 37.82,34.95 36.41,34.95 36.41,32.51 37.97,32.51
3V3D on L3_PWR: 18.8,51.87 18.8,1.28 44.03,1.28 44.03,19.98 29.25,19.98 29.25,23.3 37.8,31.85 43.97,31.85 44.03,31.92 44.03,51.87 ; 1 cut-out
5V_ARD on L3_PWR: 45.29,1.27 45.29,21.21 30.49,21.21 30.49,22.71 38.38,30.59 45.29,30.59 45.29,52.07 82.36,52.07 82.36,1.27
DGND on TOP: 44.41,8.03 44.41,6.78 46.7,6.78 47.12,6.36 49.99,6.36 49.99,7.89 47.33,7.89 46.76,8.46 45.57,8.46 45.55,8.45 45.55,8.03
DGND on L2_GND: 1.27,1.27 1.27,52.07 82.36,52.07 82.36,1.27 ; 1 cut-out
GND_ISO on L2_GND: 94.68,1.27 94.68,1.27 90.37,1.27 90.37,52.07 94.68,52.07 120.59,52.07 120.59,1.27 ; 1 cut-out
I_PWR on L3_PWR: 120.59,52.07 120.59,1.28 90.37,1.28 90.37,52.07 ; 1 cut-out
IOREF on TOP: 45.58,10.08 45.58,9 49.97,9 49.97,10.25 49.66,10.57 46.06,10.57
NI_PWR on L3_PWR: 1.27,52.07 1.27,1.27 17.53,1.27 17.53,52.07

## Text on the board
BOTTOM: 08-049100 REV C Z | SECONDARY SIDE
TOP: 08-049100 REV C Z | PRIMARY SIDE
Ref Des/Silkscreen Top: EVAL-CN0416-ARDZ  REV C Z | POWER | LT2865 | PWMH | AUTO-ENABLE SELECTORS | 1 | ADDR_SELECT | HEX SWITCH | PWML | ANALOG | ADM2682 | NON-ISOLATED PLANE | ISOLATED PLANE | HALF NON_ISO | FULL NON_ISO | FULL ISO | HALF ISO | HALF | FULL | TERM | OPEN
PAGE_OUTLINE: N/A | R. MACDONALD | M.THOREN | A.AGENA | K.JABATAN | G.MANTALA | 02MAY07 | 23APR18 | 01DEC12 | 02JAN18 | 30APR18 | B | B2 | C | CHANGES AS PER ECR#081020 | CHANGES AS PER ECR#084660 | CHANGES AS PER ECR#084906 | 10OCT18 | 29JAN19 | 01FEB19 | A.CATAPANG | EVAL BOARD Z | EVAL-CN0416-ARDZ
DIMENSION: DIA MAX | REF
User.11: 5.    DO NOT CUT THE EXCESS PINS OF THE FOLLOWING CONNECTORS: | 5.    SHORT PIN1 AND PIN2 OF THE  FOLLOWING SOLDER LINKS. | E. P7 | D. P3 | C. P10 | A. P8 | B. P9 | D. JP10 | C. JP8 | A. JP4 | B. JP6
User.17: L2 GND | 08-      -07
User.18: L3 PWR | 08-      -08
User.45: o | R | S | H | L3 | XDC_1 | D1 | TP2 | L1 | B1 | R8 | R7 | L2 | C25 | TP1 | U5 | U1 | U4 | B2 | R3 | D4 | A | Q6 | X2 | Q10 | Q1 | IOREF | Q8 | R68 | J1 | J2 | RESET | R66 | C20 | X1 | U2 | J4 | J3 | R9 | U6 | R6 | R65 | C29 | _1 | J5 | J6 | R17 | R16 | Q2 | R43 | R47 | U3 | R39 | R40 | R58 | R36 | SPI | R33 | R61 | R29 | R57 | R28 | R50 | R54 | R48 | J_UU | R41 | R53 | R44 | J_BL | R23 | R27 | R30 | R32 | R18 | XPmod2 | XPmod1 | R21 | C17 | C18 | Q7 | C16 | R49 | C1 | D2 | R45 | R55 | R4 | R1 | R52 | R69 | R2 | Q3 | R5 | C19 | C4 | R31 | R63 | C2 | R70 | C9 | R34 | C8 | C27 | C23 | C3 | R51 | D3 | C6 | R67 | C5 | Q11 | Q9 | R62 | C24 | C30 | R15 | C26 | C28 | R11 | C10 | C7 | L4 | C14 | R64 | C12 | C21 | DGND_AGND1 | C15 | R14 | C13 | C11 | R10 | R19 | R25 | Q5 | Q4 | R20 | R26 | R12 | R13 | XUUSB1 | XDUSB1 | SCL | SDA | AREF | LED1 | NC | SCK | MISO | MOSI | 3.3V | SS | 5V | P0.5 | LED4 | P0.4 | Vin | PWM5 | PWM4 | PWM3 | A0 | A1 | PWM2 | A2 | PWM1 | PWM0 | A3 | A4 | TX1 | A5 | RX1 | A6 | A7 | REFnSel | R60 | A8 | P1.0 | R46 | R59 | A9 | P1.1 | R42 | J_BL_UU | R56 | A10 | P1.2 | LED2 | P1.3 | A11 | R37 | LED3 | DAC | R22 | G_SW | R38 | J_D_U | R24 | VREF+ | VREF- | R35 | C22 | BOOT | 2 | 1 | 9 | 10 | 8 | 6 | 12 | 7 | EVAL-ADUCM360-ARDZ-Rev.1.0 | PWMH | POWER | PWML | ADCL | COMMUNICATION | ADCH | GND | 5 | . | p | l | i | a | n | t | C | m | ANALOG | FIGURE | SIZE | 14.0 | 31.0 | 35.0 | 45.0 | 55.0 | 60.0 | 126.0 | 128.0 | PLATED | NON-PLATED | FINISHED HOLES IN MILS | ALL UNITS ARE IN MILS | QTY | 68 | 76 | 58 | 4 | TOLERANCE/NOTES
